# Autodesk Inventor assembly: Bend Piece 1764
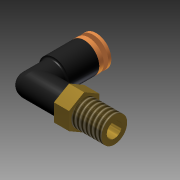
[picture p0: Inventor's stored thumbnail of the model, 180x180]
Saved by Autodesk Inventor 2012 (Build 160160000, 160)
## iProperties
Created: 2010-02
Part Number: Bend Piece 1764
Document SubType Name: Assembly
Designer: jgehrig
Author: jgehrig
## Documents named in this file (4)
- R:\CAD Archives\Pneumatics_1764\Soloniod_1764\Pneumatics_Bend_Piece_1764\Pneumatic_Bend_Piece_1764.iam
- R:\CAD Archives\Pneumatics_1764\Soloniod_1764\Pneumatics_Bend_Piece_1764\Pneumatics_Bend_Piece_1764.ipt
- R:\CAD Archives\Pneumatics_1764\Soloniod_1764\Pneumatics_Bend_Piece_1764\Pneumatic_Screw_Part_1764.ipt
- R:\CAD Archives\Pneumatics_1764\Soloniod_1764\Pneumatics_Bend_Piece_1764\Pneumatic_Screw_Part_2_1764.ipt
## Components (3 placed, 3 different names)
1. Pneumatics_Bend_Piece_1764:1 — Insert:1, Insert:2
2. Pneumatic_Screw_Part_1764:1 — Insert:2
3. Pneumatic_Screw_Part_2_1764:1 — Insert:1
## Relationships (2: Insert 2)
- Insert:1: Pneumatics_Bend_Piece_1764:1 ↔ Pneumatic_Screw_Part_2_1764:1
- Insert:2: Pneumatics_Bend_Piece_1764:1 ↔ Pneumatic_Screw_Part_1764:1
